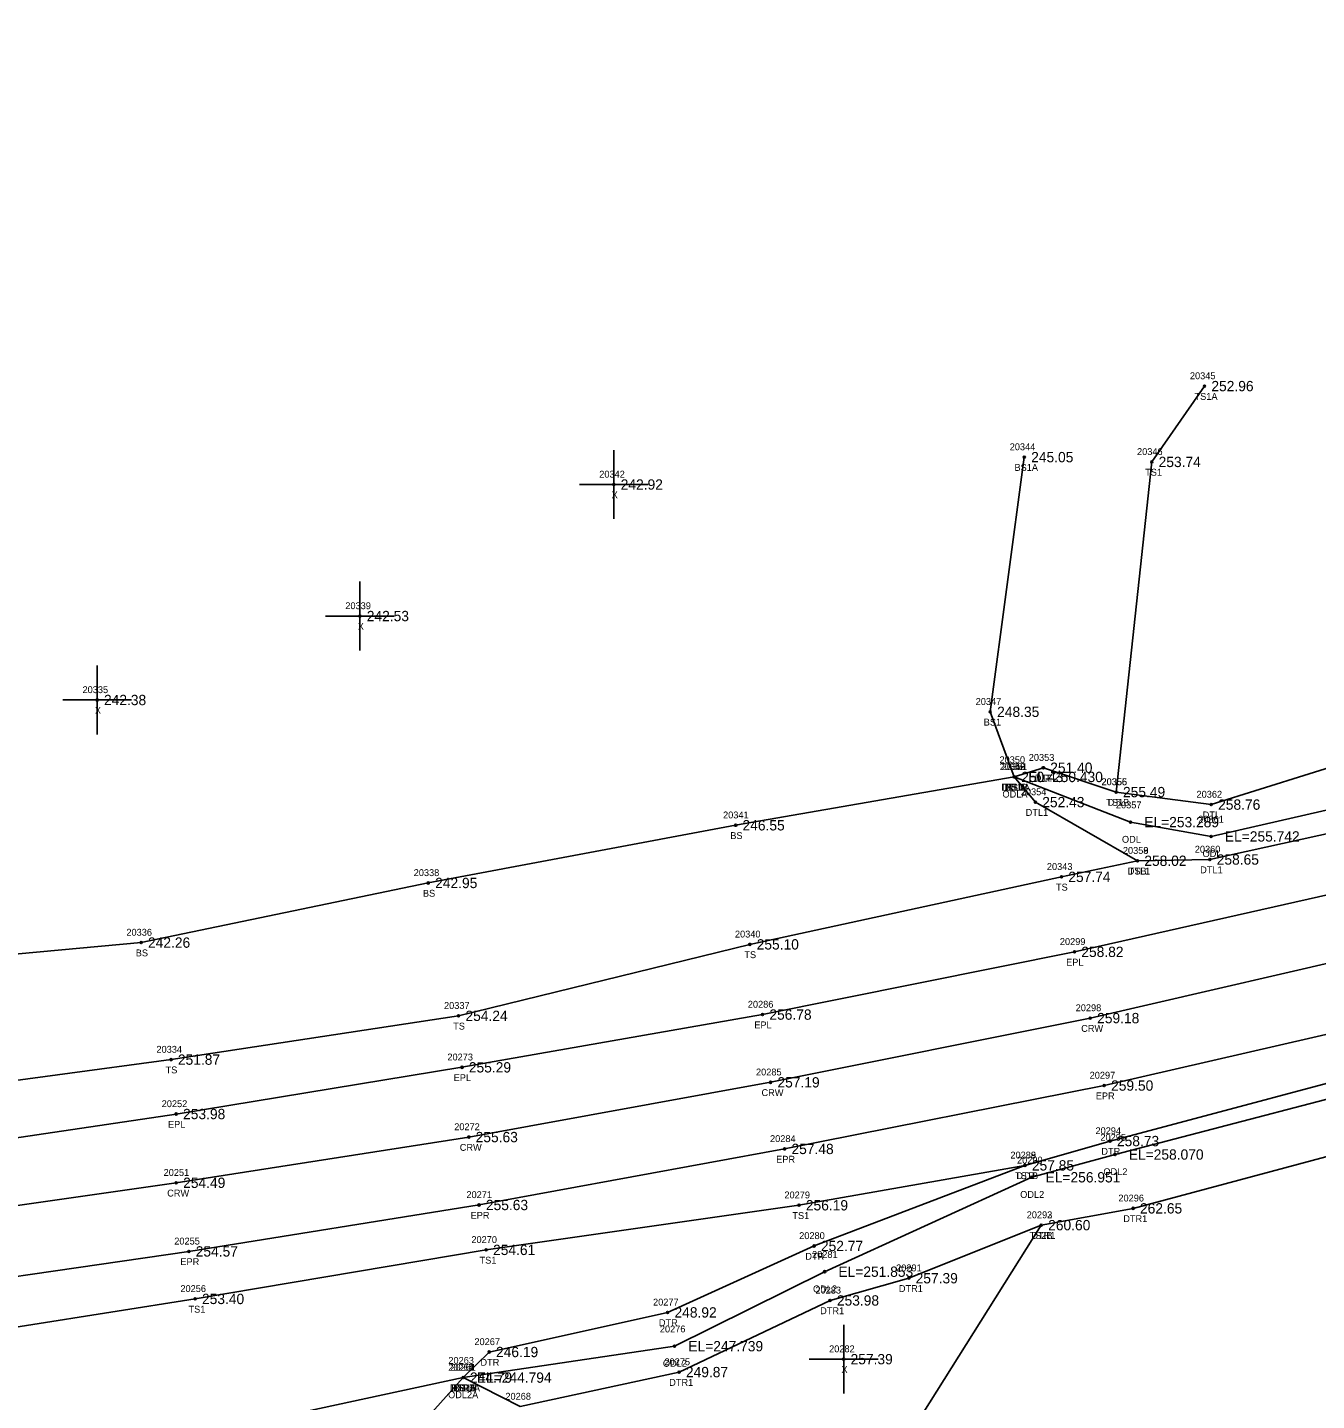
# Model space of a CAD drawing. Extents: x 2275563 to 2277161, y 1075719 to 1076412.
# Drawn here: x 2276514 to 2276701.4, y 1076061.7 to 1076261.3 of the extents above; entities that cross this region are included whole.
import ezdxf

# ---------------------------------------------------------------- set-up
doc = ezdxf.new("R2010")
doc.units = 0
for name, color, linetype in [('RD_DTM_BkLn1', 7, 'Continuous'), ('RD_DTM_BkLn2', 7, 'Continuous'), ('RD_DTM_BkLn_txCode', 7, 'Continuous'), ('RD_EX_H2O', 7, 'Continuous'), ('RD_EX_H2O_txCode', 7, 'Continuous'), ('RD_EX_Misc', 7, 'Continuous'), ('RD_EX_Misc_txCode', 7, 'Continuous'), ('RD_EX_Road', 7, 'Continuous'), ('RD_EX_Road_txCode', 7, 'Continuous'), ('RD_EX_TX_H2O_ELEV', 7, 'Continuous'), ('RD_EX_TX_Misc_ELEV', 7, 'Continuous'), ('RD_EX_TX_Road_ELEV', 7, 'Continuous'), ('RD_HC_Survey_ELEV', 7, 'Continuous'), ('RD_HC_Survey_txCode', 7, 'Continuous'), ('RD_SMD_Locator', 7, 'Continuous')]:
    doc.layers.add(name, color=color, linetype=linetype)

msp = doc.modelspace()

# ---------------------------------------------------------------- linework, layer by layer
at = {"layer": 'RD_DTM_BkLn1'}
msp.add_lwpolyline([(2276380.47, 1076073.8), (2276432.36, 1076079.4), (2276487.41, 1076086.42), (2276535.62, 1076093.32), (2276578.15, 1076099.97), (2276622.03, 1076107.93), (2276668.51, 1076117.27), (2276714.2, 1076127.81), (2276762.94, 1076140.11), (2276806.88, 1076151.96), (2276854.94, 1076166.29), (2276899.73, 1076180.7), (2276952.88, 1076198.57), (2277000.46, 1076214.72), (2277057.1, 1076234.01), (2277134.93, 1076261.07)], dxfattribs=at)
at = {"layer": 'RD_DTM_BkLn2'}
for points in [[(2276685.12, 1076209.18), (2276677.45, 1076198.15), (2276672.27, 1076150.14)], [(2276658.92, 1076198.85), (2276653.97, 1076161.81), (2276657.47, 1076152.34)], [(2276352.82, 1076100.61), (2276380.25, 1076112.06), (2276428.17, 1076110.1), (2276479.59, 1076123.58), (2276530.51, 1076128.25), (2276572.26, 1076136.92), (2276616.95, 1076145.31), (2276657.47, 1076152.34)], [(2276378.73, 1076086.44), (2276379.33, 1076090.71), (2276430.69, 1076098.18), (2276485.24, 1076104.54), (2276534.86, 1076111.23), (2276576.67, 1076117.6), (2276619.01, 1076127.99), (2276664.32, 1076137.81), (2276675.37, 1076140.15)], [(2276381.23, 1076060.52), (2276384.72, 1076057.35), (2276432.14, 1076059.24), (2276489.29, 1076068.7), (2276538.36, 1076076.43), (2276580.68, 1076083.56), (2276626.16, 1076090.05), (2276659.02, 1076095.85)], [(2276569.56, 1075978.62), (2276587.82, 1075999.87), (2276622.72, 1076028.54), (2276636.37, 1076047.35), (2276661.39, 1076087.16)], [(2276373.09, 1076038.49), (2276389.65, 1076038.07), (2276402.95, 1076045.94), (2276434.46, 1076042.78), (2276488.57, 1076051.06), (2276535.54, 1076055.99), (2276577.32, 1076064.99)], [(2276519.11, 1075988.97), (2276536.46, 1076029.68), (2276569.5, 1076056.25), (2276577.32, 1076064.99)]]:
    msp.add_lwpolyline(points, dxfattribs=at)
at = {"layer": 'RD_EX_H2O'}
for points in [[(2276657.47, 1076152.34), (2276661.69, 1076153.68), (2276672.27, 1076150.14), (2276686.1, 1076148.32), (2276707.44, 1076155), (2276757.51, 1076168.89), (2276800.48, 1076181.68), (2276845.56, 1076196.09), (2276892.53, 1076210.89), (2276946.81, 1076230.38), (2276991.46, 1076246.85), (2277048.24, 1076266.02), (2277127.1, 1076291.82)], [(2276657.47, 1076152.34), (2276674.36, 1076145.77), (2276686.08, 1076143.69), (2276709.61, 1076149.05), (2276758.42, 1076158.57), (2276802.68, 1076170.14), (2276849.17, 1076183.99), (2276894.22, 1076200.15), (2276947.41, 1076217.63), (2276994.62, 1076234.82), (2277050.9, 1076254.6), (2277129.78, 1076281.89)], [(2276657.47, 1076152.34), (2276660.53, 1076148.68), (2276675.37, 1076140.15), (2276685.9, 1076140.33), (2276709.89, 1076145.63), (2276758.95, 1076156.3), (2276803.23, 1076167.04), (2276849.8, 1076180.23), (2276895.12, 1076197.46), (2276948.16, 1076214.68), (2276995.02, 1076232.39), (2277051.22, 1076251.9), (2277130.41, 1076279.08)], [(2276577.32, 1076064.99), (2276581.11, 1076068.71), (2276607.06, 1076074.47), (2276628.35, 1076084.13), (2276659.02, 1076095.85), (2276671.39, 1076099.39), (2276718.28, 1076111.88), (2276766.76, 1076124.15), (2276811.4, 1076137.27), (2276858.53, 1076152.16), (2276905.48, 1076167.47), (2276958.61, 1076184.59), (2277007.29, 1076200.4), (2277063.09, 1076219.53), (2277141.85, 1076245.35)], [(2276577.32, 1076064.99), (2276608.07, 1076069.56), (2276629.89, 1076080.39), (2276660.01, 1076094.12), (2276672.11, 1076097.43), (2276718.92, 1076109.66), (2276767.33, 1076122.4), (2276812.13, 1076135.39), (2276859.85, 1076149.89), (2276906.21, 1076164.41), (2276959.66, 1076181.81), (2277008.45, 1076198), (2277064.73, 1076216.97), (2277142.57, 1076243.16)], [(2276577.32, 1076064.99), (2276585.61, 1076060.77), (2276608.72, 1076065.79), (2276630.67, 1076076.21), (2276642.12, 1076079.44), (2276661.39, 1076087.16), (2276674.74, 1076089.6), (2276720.85, 1076101.92), (2276769.56, 1076115.83), (2276815.16, 1076127.06), (2276862.66, 1076139.65), (2276909.53, 1076154.75), (2276961.42, 1076172.61), (2277010.89, 1076191.18), (2277066.25, 1076211.87), (2277143.49, 1076241.1)]]:
    msp.add_lwpolyline(points, dxfattribs=at)
at = {"layer": 'RD_EX_Misc'}
for p, q in [((2276599.24, 1076189.87), (2276599.24, 1076199.87)), ((2276594.24, 1076194.87), (2276604.24, 1076194.87)), ((2276562.32, 1076170.74), (2276562.32, 1076180.74)), ((2276557.32, 1076175.74), (2276567.32, 1076175.74)), ((2276524.11, 1076158.53), (2276524.11, 1076168.53)), ((2276519.11, 1076163.53), (2276529.11, 1076163.53)), ((2276632.66, 1076062.67), (2276632.66, 1076072.67)), ((2276627.66, 1076067.67), (2276637.66, 1076067.67))]:
    msp.add_line(p, q, dxfattribs=at)
at = {"layer": 'RD_EX_Road'}
for points in [[(2276379.21, 1076084.39), (2276432.25, 1076089.28), (2276486.22, 1076095.98), (2276535.61, 1076103.32), (2276577.16, 1076110.11), (2276620.86, 1076117.78), (2276666.21, 1076126.9), (2276712, 1076137.22), (2276761.13, 1076149.72), (2276804.56, 1076161.71), (2276851.24, 1076175.53), (2276896.93, 1076190.53), (2276950.19, 1076208.22), (2276997.45, 1076224.3), (2277053.81, 1076243.77), (2277132.14, 1076270.77)], [(2276381.27, 1076063.04), (2276433.15, 1076069.16), (2276488.59, 1076076.23), (2276537.45, 1076083.34), (2276579.64, 1076090.09), (2276624.07, 1076098.24), (2276670.54, 1076107.46), (2276716.67, 1076118.09), (2276765.18, 1076130.28), (2276809.58, 1076142.25), (2276856.93, 1076156.58), (2276903.53, 1076171.63), (2276957.27, 1076189.46), (2277005.85, 1076206.01), (2277060.98, 1076225.07), (2277139.5, 1076252.36)]]:
    msp.add_lwpolyline(points, dxfattribs=at)
at = {"layer": 'RD_SMD_Locator'}
for centre in [(2276685.12, 1076209.18), (2276658.92, 1076198.85), (2276677.45, 1076198.15), (2276599.24, 1076194.87), (2276562.32, 1076175.74), (2276524.11, 1076163.53), (2276653.97, 1076161.81), (2276657.47, 1076152.34), (2276657.47, 1076152.34), (2276657.47, 1076152.34), (2276657.47, 1076152.34), (2276657.47, 1076152.34), (2276661.69, 1076153.68), (2276672.27, 1076150.14), (2276672.27, 1076150.14), (2276660.53, 1076148.68), (2276686.1, 1076148.32), (2276616.95, 1076145.31), (2276674.36, 1076145.77), (2276686.08, 1076143.69), (2276675.37, 1076140.15), (2276675.37, 1076140.15), (2276685.9, 1076140.33), (2276572.26, 1076136.92), (2276664.32, 1076137.81), (2276530.51, 1076128.25), (2276619.01, 1076127.99), (2276666.21, 1076126.9), (2276576.67, 1076117.6), (2276620.86, 1076117.78), (2276668.51, 1076117.27), (2276534.86, 1076111.23), (2276577.16, 1076110.11), (2276622.03, 1076107.93), (2276670.54, 1076107.46), (2276535.61, 1076103.32), (2276578.15, 1076099.97), (2276624.07, 1076098.24), (2276671.39, 1076099.39), (2276672.11, 1076097.43), (2276659.02, 1076095.85), (2276659.02, 1076095.85), (2276660.01, 1076094.12), (2276535.62, 1076093.32), (2276579.64, 1076090.09), (2276626.16, 1076090.05), (2276674.74, 1076089.6), (2276661.39, 1076087.16), (2276661.39, 1076087.16), (2276628.35, 1076084.13), (2276537.45, 1076083.34), (2276580.68, 1076083.56), (2276629.89, 1076080.39), (2276642.12, 1076079.44), (2276538.36, 1076076.43), (2276630.67, 1076076.21), (2276607.06, 1076074.47), (2276581.11, 1076068.71), (2276608.07, 1076069.56), (2276632.66, 1076067.67), (2276577.32, 1076064.99), (2276577.32, 1076064.99), (2276577.32, 1076064.99), (2276577.32, 1076064.99), (2276577.32, 1076064.99), (2276608.72, 1076065.79)]:
    msp.add_circle(centre, 0.15, dxfattribs=at)

# ---------------------------------------------------------------- texts
at = {"layer": 'RD_DTM_BkLn_txCode'}
for s, p in [('20345', (2276683, 1076210.18)), ('TS1A', (2276683.67, 1076207.18)), ('20344', (2276656.8, 1076199.85)), ('20346', (2276675.31, 1076199.15)), ('BS1A', (2276657.49, 1076196.85)), ('TS1', (2276676.49, 1076196.15)), ('20347', (2276651.85, 1076162.81)), ('BS1', (2276653.02, 1076159.81)), ('20348', (2276655.35, 1076153.34)), ('20349', (2276655.35, 1076153.34)), ('20355', (2276670.16, 1076151.14)), ('BS1B', (2276656.05, 1076150.34)), ('BSB', (2276656.22, 1076150.34)), ('TS1B', (2276670.84, 1076148.14)), ('20341', (2276615.12, 1076146.31)), ('BS', (2276616.17, 1076143.31)), ('20358', (2276673.25, 1076141.15)), ('20338', (2276570.14, 1076137.92)), ('20343', (2276662.2, 1076138.81)), ('TSB', (2276674.1, 1076138.15)), ('TS', (2276663.52, 1076135.81)), ('BS', (2276571.48, 1076134.92)), ('20336', (2276528.37, 1076129.25)), ('20340', (2276616.85, 1076128.99)), ('BS', (2276529.73, 1076126.25)), ('TS', (2276618.22, 1076125.99)), ('20337', (2276574.55, 1076118.6)), ('TS', (2276575.88, 1076115.6)), ('20334', (2276532.74, 1076112.23)), ('TS', (2276534.07, 1076109.23)), ('20288', (2276656.9, 1076096.85)), ('TS1B', (2276657.58, 1076093.85)), ('20279', (2276624.04, 1076091.05)), ('TS1', (2276625.2, 1076088.05)), ('20292', (2276659.27, 1076088.16)), ('TS2B', (2276659.67, 1076085.16)), ('20270', (2276578.53, 1076084.56)), ('TS1', (2276579.72, 1076081.56)), ('20256', (2276536.22, 1076077.43)), ('TS1', (2276537.4, 1076074.43)), ('20262', (2276575.18, 1076065.99)), ('20261', (2276575.46, 1076065.99)), ('BS2B', (2276575.62, 1076062.99)), ('BS1B', (2276575.9, 1076062.99))]:
    msp.add_text(s, height=1, dxfattribs=at).set_placement(p)
at = {"layer": 'RD_EX_H2O_txCode'}
for s, p in [('20350', (2276655.31, 1076154.34)), ('20352', (2276655.35, 1076153.34)), ('20351', (2276655.63, 1076153.34)), ('20353', (2276659.57, 1076154.68)), ('DTL', (2276660.44, 1076151.68)), ('20356', (2276670.13, 1076151.14)), ('DTL1A', (2276655.57, 1076150.34)), ('ODLA', (2276655.74, 1076149.34)), ('DTLA', (2276655.74, 1076150.34)), ('20354', (2276658.41, 1076149.68)), ('20362', (2276683.96, 1076149.32)), ('DTL', (2276671.03, 1076148.14)), ('20357', (2276672.24, 1076147.77)), ('DTL1', (2276659.12, 1076146.68)), ('20361', (2276684.22, 1076145.69)), ('DTL', (2276684.86, 1076146.32)), ('ODL', (2276673.12, 1076142.77)), ('20359', (2276673.25, 1076141.15)), ('20360', (2276683.71, 1076141.33)), ('ODL', (2276684.84, 1076140.69)), ('DTL1', (2276673.96, 1076138.15)), ('DTL1', (2276684.49, 1076138.33)), ('20294', (2276669.27, 1076100.39)), ('20295', (2276669.99, 1076099.43)), ('DTR', (2276670.12, 1076097.39)), ('20289', (2276656.9, 1076096.85)), ('20290', (2276657.86, 1076096.12)), ('DTR', (2276657.75, 1076093.85)), ('ODL2', (2276670.42, 1076094.43)), ('ODL2', (2276658.32, 1076091.12)), ('20296', (2276672.6, 1076090.6)), ('20293', (2276659.27, 1076088.16)), ('DTR1', (2276673.31, 1076087.6)), ('20280', (2276626.19, 1076085.13)), ('DTR1', (2276659.95, 1076085.16)), ('DTR', (2276627.08, 1076082.13)), ('20281', (2276628.06, 1076082.39)), ('20291', (2276640.28, 1076080.44)), ('ODL2', (2276628.2, 1076077.39)), ('20283', (2276628.55, 1076077.21)), ('DTR1', (2276640.68, 1076077.44)), ('20277', (2276604.94, 1076075.47)), ('DTR1', (2276629.24, 1076074.21)), ('DTR', (2276605.79, 1076072.47)), ('20276', (2276605.93, 1076071.56)), ('20267', (2276578.97, 1076069.71)), ('20263', (2276575.18, 1076066.99)), ('20264', (2276575.18, 1076065.99)), ('20265', (2276575.18, 1076065.99)), ('DTR', (2276579.85, 1076066.71)), ('ODL2', (2276606.37, 1076066.56)), ('20275', (2276606.6, 1076066.79)), ('DTR1', (2276607.29, 1076063.79)), ('ODL2A', (2276575.14, 1076061.99)), ('DTR1A', (2276575.4, 1076062.99)), ('DTRA', (2276575.56, 1076062.99)), ('20268', (2276583.47, 1076061.77))]:
    msp.add_text(s, height=1, dxfattribs=at).set_placement(p)
at = {"layer": 'RD_EX_Misc_txCode'}
for s, p in [('20342', (2276597.12, 1076195.87)), ('X', (2276598.92, 1076192.87)), ('20339', (2276560.2, 1076176.74)), ('X', (2276562.01, 1076173.74)), ('20335', (2276521.99, 1076164.53)), ('X', (2276523.79, 1076161.53)), ('20282', (2276630.54, 1076068.67)), ('X', (2276632.34, 1076065.67))]:
    msp.add_text(s, height=1, dxfattribs=at).set_placement(p)
at = {"layer": 'RD_EX_Road_txCode'}
for s, p in [('20299', (2276664.09, 1076127.9)), ('EPL', (2276665, 1076124.9)), ('20286', (2276618.72, 1076118.78)), ('EPL', (2276619.66, 1076115.78)), ('20273', (2276575.04, 1076111.11)), ('EPL', (2276575.95, 1076108.11)), ('20297', (2276668.42, 1076108.46)), ('EPR', (2276669.31, 1076105.46)), ('20252', (2276533.5, 1076104.32)), ('EPL', (2276534.41, 1076101.32)), ('20284', (2276621.95, 1076099.24)), ('EPR', (2276622.84, 1076096.24)), ('20271', (2276577.81, 1076091.09)), ('EPR', (2276578.41, 1076088.09)), ('20255', (2276535.33, 1076084.34)), ('EPR', (2276536.22, 1076081.34))]:
    msp.add_text(s, height=1, dxfattribs=at).set_placement(p)
at = {"layer": 'RD_EX_TX_H2O_ELEV'}
for s, p in [('251.40', (2276662.69, 1076152.93)), ('250.43', (2276658.47, 1076151.59)), ('250.43', (2276658.47, 1076151.59)), ('EL=250.430', (2276659.47, 1076151.59)), ('255.49', (2276673.27, 1076149.39)), ('252.43', (2276661.53, 1076147.93)), ('258.76', (2276687.1, 1076147.57)), ('EL=253.289', (2276676.36, 1076145.02)), ('EL=255.742', (2276688.08, 1076142.94)), ('258.02', (2276676.37, 1076139.4)), ('258.65', (2276686.9, 1076139.58)), ('258.73', (2276672.39, 1076098.64)), ('EL=258.070', (2276674.11, 1076096.68)), ('257.85', (2276660.02, 1076095.1)), ('EL=256.951', (2276662.01, 1076093.37)), ('262.65', (2276675.74, 1076088.85)), ('260.60', (2276662.39, 1076086.41)), ('252.77', (2276629.35, 1076083.38)), ('EL=251.853', (2276631.89, 1076079.64)), ('257.39', (2276643.12, 1076078.69)), ('253.98', (2276631.67, 1076075.46)), ('248.92', (2276608.06, 1076073.72)), ('EL=247.739', (2276610.07, 1076068.81)), ('246.19', (2276582.11, 1076067.96)), ('249.87', (2276609.72, 1076065.04)), ('244.79', (2276578.32, 1076064.24)), ('244.79', (2276578.32, 1076064.24)), ('EL=244.794', (2276579.32, 1076064.24))]:
    msp.add_text(s, height=1.5, dxfattribs=at).set_placement(p)
at = {"layer": 'RD_EX_TX_Misc_ELEV'}
for s, p in [('252.96', (2276686.12, 1076208.43)), ('245.05', (2276659.92, 1076198.1)), ('253.74', (2276678.45, 1076197.4)), ('242.92', (2276600.24, 1076194.12)), ('242.53', (2276563.32, 1076174.99)), ('242.38', (2276525.11, 1076162.78)), ('248.35', (2276654.97, 1076161.06)), ('250.43', (2276658.47, 1076151.59)), ('250.43', (2276658.47, 1076151.59)), ('255.49', (2276673.27, 1076149.39)), ('246.55', (2276617.95, 1076144.56)), ('258.02', (2276676.37, 1076139.4)), ('257.74', (2276665.32, 1076137.06)), ('242.95', (2276573.26, 1076136.17)), ('242.26', (2276531.51, 1076127.5)), ('255.10', (2276620.01, 1076127.24)), ('254.24', (2276577.67, 1076116.85)), ('251.87', (2276535.86, 1076110.48)), ('257.85', (2276660.02, 1076095.1)), ('256.19', (2276627.16, 1076089.3)), ('260.60', (2276662.39, 1076086.41)), ('254.61', (2276581.68, 1076082.81)), ('253.40', (2276539.36, 1076075.68)), ('257.39', (2276633.66, 1076066.92)), ('244.79', (2276578.32, 1076064.24)), ('244.79', (2276578.32, 1076064.24))]:
    msp.add_text(s, height=1.5, dxfattribs=at).set_placement(p)
at = {"layer": 'RD_EX_TX_Road_ELEV'}
for s, p in [('258.82', (2276667.21, 1076126.15)), ('256.78', (2276621.86, 1076117.03)), ('255.29', (2276578.16, 1076109.36)), ('259.50', (2276671.54, 1076106.71)), ('253.98', (2276536.61, 1076102.57)), ('257.48', (2276625.07, 1076097.49)), ('255.63', (2276580.64, 1076089.34)), ('254.57', (2276538.45, 1076082.59))]:
    msp.add_text(s, height=1.5, dxfattribs=at).set_placement(p)
at = {"layer": 'RD_HC_Survey_ELEV'}
for s, p in [('259.18', (2276669.51, 1076116.52)), ('257.19', (2276623.03, 1076107.18)), ('255.63', (2276579.15, 1076099.22)), ('254.49', (2276536.62, 1076092.57))]:
    msp.add_text(s, height=1.5, dxfattribs=at).set_placement(p)
at = {"layer": 'RD_HC_Survey_txCode'}
for s, p in [('20298', (2276666.39, 1076118.27)), ('CRW', (2276667.19, 1076115.27)), ('20285', (2276619.91, 1076108.93)), ('CRW', (2276620.71, 1076105.93)), ('20272', (2276576.03, 1076100.97)), ('CRW', (2276576.84, 1076097.97)), ('20251', (2276533.78, 1076094.32)), ('CRW', (2276534.3, 1076091.32))]:
    msp.add_text(s, height=1, dxfattribs=at).set_placement(p)

doc.saveas('drawing.dxf')
